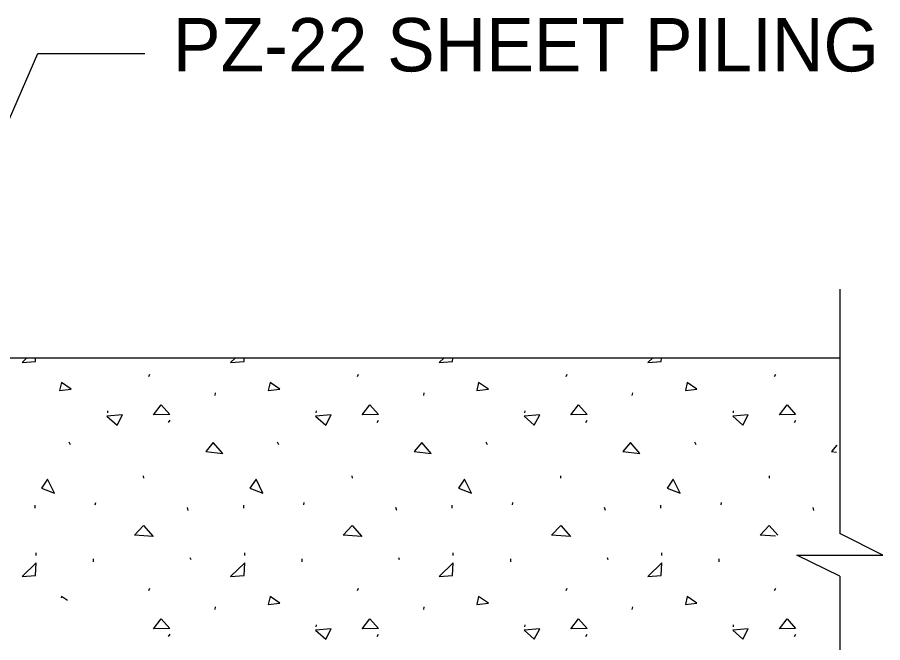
# Model space of a CAD drawing. Extents: x 22369.6 to 22384.3, y 22369.6 to 22381.8.
# Drawn here: x 22375.262 to 22376.018, y 22379.363 to 22379.909 of the extents above; entities that cross this region are included whole.
import ezdxf

# ---------------------------------------------------------------- set-up
doc = ezdxf.new("R2010")
doc.units = 0
for name, color, linetype in [('Level 1', 7, 'Continuous'), ('Level 10', 7, 'Continuous'), ('Level 4', 7, 'Continuous'), ('Level 8', 7, 'Continuous')]:
    doc.layers.add(name, color=color, linetype=linetype)

msp = doc.modelspace()

# ---------------------------------------------------------------- linework, layer by layer
at = {"layer": 'Level 1'}
for p, q in [((22375.05626, 22379.36384), (22375.28013, 22379.87777)), ((22375.28013, 22379.87777), (22375.37359, 22379.87777)), ((22375.98076, 22379.67156), (22375.98076, 22379.45803)), ((22375.98076, 22379.42065), (22375.98076, 22378.74796))]:
    msp.add_line(p, q, dxfattribs=at)
msp.add_lwpolyline([(22375.98076, 22379.42065), (22375.94326, 22379.43928), (22376.01818, 22379.43928), (22375.98076, 22379.45803)], dxfattribs=at)
at = {"layer": 'Level 10'}
msp.add_line((22375.98076, 22379.61141), (22375.02114, 22379.61141), dxfattribs=at)
at = {"layer": 'Level 8'}
for p, q in [((22375.37715, 22379.59544), (22375.37807, 22379.59739)), ((22375.55936, 22379.59544), (22375.56028, 22379.59739)), ((22375.74157, 22379.59544), (22375.74249, 22379.59739)), ((22375.92378, 22379.59544), (22375.9247, 22379.59739)), ((22375.43499, 22379.57864), (22375.43536, 22379.58106)), ((22375.6172, 22379.57864), (22375.61757, 22379.58106)), ((22375.7994, 22379.57864), (22375.79978, 22379.58106)), ((22375.34115, 22379.56344), (22375.34132, 22379.56527)), ((22375.52336, 22379.56344), (22375.52353, 22379.56527)), ((22375.70557, 22379.56344), (22375.70574, 22379.56527)), ((22375.88778, 22379.56344), (22375.88795, 22379.56527)), ((22375.39436, 22379.5551), (22375.39561, 22379.55719)), ((22375.57657, 22379.5551), (22375.57782, 22379.55719)), ((22375.75878, 22379.5551), (22375.76003, 22379.55719)), ((22375.94099, 22379.5551), (22375.94224, 22379.55719)), ((22375.30853, 22379.5356), (22375.3074, 22379.53781)), ((22375.49074, 22379.5356), (22375.48961, 22379.53781)), ((22375.67295, 22379.5356), (22375.67182, 22379.53781)), ((22375.85515, 22379.5356), (22375.85403, 22379.53781)), ((22375.3727, 22379.50656), (22375.37253, 22379.5086)), ((22375.5549, 22379.50656), (22375.55474, 22379.5086)), ((22375.73711, 22379.50656), (22375.73695, 22379.5086)), ((22375.91932, 22379.50656), (22375.91915, 22379.5086)), ((22375.33032, 22379.48319), (22375.33065, 22379.48506)), ((22375.51253, 22379.48319), (22375.51286, 22379.48506)), ((22375.69474, 22379.48319), (22375.69507, 22379.48506)), ((22375.87695, 22379.48319), (22375.87728, 22379.48506)), ((22375.27778, 22379.48023), (22375.27778, 22379.48273)), ((22375.41149, 22379.47823), (22375.41078, 22379.48073)), ((22375.45999, 22379.48023), (22375.45999, 22379.48273)), ((22375.5937, 22379.47823), (22375.59299, 22379.48073)), ((22375.6422, 22379.48023), (22375.6422, 22379.48273)), ((22375.7759, 22379.47823), (22375.7752, 22379.48073)), ((22375.8244, 22379.48023), (22375.8244, 22379.48273)), ((22375.95811, 22379.47823), (22375.9574, 22379.48073)), ((22375.27865, 22379.43877), (22375.27865, 22379.4411)), ((22375.46086, 22379.43877), (22375.46086, 22379.4411)), ((22375.64307, 22379.43877), (22375.64307, 22379.4411)), ((22375.82528, 22379.43877), (22375.82528, 22379.4411)), ((22375.32878, 22379.43339), (22375.32878, 22379.43589)), ((22375.41399, 22379.4351), (22375.41328, 22379.43689)), ((22375.51099, 22379.43339), (22375.51099, 22379.43589)), ((22375.5962, 22379.4351), (22375.59549, 22379.43689)), ((22375.6932, 22379.43339), (22375.6932, 22379.43589)), ((22375.7784, 22379.4351), (22375.7777, 22379.43689)), ((22375.8754, 22379.43339), (22375.8754, 22379.43589)), ((22375.37715, 22379.40839), (22375.37807, 22379.41035)), ((22375.55936, 22379.40839), (22375.56028, 22379.41035)), ((22375.74157, 22379.40839), (22375.74249, 22379.41035)), ((22375.92378, 22379.40839), (22375.9247, 22379.41035)), ((22375.43499, 22379.3916), (22375.43536, 22379.39402)), ((22375.6172, 22379.3916), (22375.61757, 22379.39402)), ((22375.7994, 22379.3916), (22375.79978, 22379.39402)), ((22375.52336, 22379.37639), (22375.52353, 22379.37823)), ((22375.70557, 22379.37639), (22375.70574, 22379.37823)), ((22375.88778, 22379.37639), (22375.88795, 22379.37823)), ((22375.39436, 22379.36806), (22375.39561, 22379.37014)), ((22375.57657, 22379.36806), (22375.57782, 22379.37014)), ((22375.75878, 22379.36806), (22375.76003, 22379.37014)), ((22375.94099, 22379.36806), (22375.94224, 22379.37014))]:
    msp.add_line(p, q, dxfattribs=at)
for points in [[(22375.27032, 22379.61141), (22375.26632, 22379.60752)], [(22375.26632, 22379.60752), (22375.27803, 22379.60844)], [(22375.27803, 22379.60844), (22375.27821, 22379.61141)], [(22375.45253, 22379.61141), (22375.44853, 22379.60752)], [(22375.44853, 22379.60752), (22375.46024, 22379.60844)], [(22375.46024, 22379.60844), (22375.46041, 22379.61141)], [(22375.63473, 22379.61141), (22375.63074, 22379.60752)], [(22375.63074, 22379.60752), (22375.64245, 22379.60844)], [(22375.64245, 22379.60844), (22375.64261, 22379.61141)], [(22375.81694, 22379.61141), (22375.81295, 22379.60752)], [(22375.81295, 22379.60752), (22375.82465, 22379.60844)], [(22375.82465, 22379.60844), (22375.82482, 22379.61141)], [(22375.97813, 22379.53539), (22375.97336, 22379.52973)], [(22375.97336, 22379.52973), (22375.97791, 22379.52923)], [(22375.91115, 22379.45652), (22375.91907, 22379.4651)], [(22375.91907, 22379.4651), (22375.92659, 22379.45669)], [(22375.92461, 22379.45576), (22375.91115, 22379.45652)], [(22375.30078, 22379.40298), (22375.3005, 22379.40174)], [(22375.30611, 22379.39939), (22375.30078, 22379.40298)]]:
    msp.add_lwpolyline(points, dxfattribs=at)
for points in [[(22375.29915, 22379.58302), (22375.30928, 22379.58431), (22375.30078, 22379.59002)], [(22375.48136, 22379.58302), (22375.49149, 22379.58431), (22375.48299, 22379.59002)], [(22375.66357, 22379.58302), (22375.6737, 22379.58431), (22375.6652, 22379.59002)], [(22375.84578, 22379.58302), (22375.8559, 22379.58431), (22375.8474, 22379.59002)], [(22375.38128, 22379.56169), (22375.38799, 22379.57056), (22375.39553, 22379.56202)], [(22375.56349, 22379.56169), (22375.5702, 22379.57056), (22375.57774, 22379.56202)], [(22375.7457, 22379.56169), (22375.7524, 22379.57056), (22375.75995, 22379.56202)], [(22375.9279, 22379.56169), (22375.93461, 22379.57056), (22375.94215, 22379.56202)], [(22375.34053, 22379.56073), (22375.3494, 22379.55281), (22375.35415, 22379.56169)], [(22375.52274, 22379.56073), (22375.53161, 22379.55281), (22375.53636, 22379.56169)], [(22375.70495, 22379.56073), (22375.71382, 22379.55281), (22375.71857, 22379.56169)], [(22375.88715, 22379.56073), (22375.89603, 22379.55281), (22375.90078, 22379.56169)], [(22375.44161, 22379.5281), (22375.43336, 22379.5376), (22375.42674, 22379.52973)], [(22375.62382, 22379.5281), (22375.61557, 22379.5376), (22375.60895, 22379.52973)], [(22375.80603, 22379.5281), (22375.79778, 22379.5376), (22375.79115, 22379.52973)], [(22375.2832, 22379.49773), (22375.29457, 22379.49331), (22375.28857, 22379.5056)], [(22375.4654, 22379.49773), (22375.47678, 22379.49331), (22375.47078, 22379.5056)], [(22375.64761, 22379.49773), (22375.65899, 22379.49331), (22375.65299, 22379.5056)], [(22375.82982, 22379.49773), (22375.8412, 22379.49331), (22375.8352, 22379.5056)], [(22375.36453, 22379.45652), (22375.37245, 22379.4651), (22375.38095, 22379.4556)], [(22375.54674, 22379.45652), (22375.55465, 22379.4651), (22375.56315, 22379.4556)], [(22375.72895, 22379.45652), (22375.73686, 22379.4651), (22375.74536, 22379.4556)], [(22375.27803, 22379.42139), (22375.27865, 22379.43252), (22375.26632, 22379.42048)], [(22375.46024, 22379.42139), (22375.46086, 22379.43252), (22375.44853, 22379.42048)], [(22375.64245, 22379.42139), (22375.64307, 22379.43252), (22375.63074, 22379.42048)], [(22375.82465, 22379.42139), (22375.82528, 22379.43252), (22375.81295, 22379.42048)], [(22375.48136, 22379.39598), (22375.49149, 22379.39727), (22375.48299, 22379.40298)], [(22375.66357, 22379.39598), (22375.6737, 22379.39727), (22375.6652, 22379.40298)], [(22375.84578, 22379.39598), (22375.8559, 22379.39727), (22375.8474, 22379.40298)], [(22375.38128, 22379.37464), (22375.38799, 22379.38352), (22375.39553, 22379.37498)], [(22375.56349, 22379.37464), (22375.5702, 22379.38352), (22375.57774, 22379.37498)], [(22375.7457, 22379.37464), (22375.7524, 22379.38352), (22375.75995, 22379.37498)], [(22375.9279, 22379.37464), (22375.93461, 22379.38352), (22375.94215, 22379.37498)], [(22375.52274, 22379.37369), (22375.53161, 22379.36577), (22375.53636, 22379.37464)], [(22375.70495, 22379.37369), (22375.71382, 22379.36577), (22375.71857, 22379.37464)], [(22375.88715, 22379.37369), (22375.89603, 22379.36577), (22375.90078, 22379.37464)]]:
    msp.add_lwpolyline(points, close=True, dxfattribs=at)

# ---------------------------------------------------------------- texts
at = {"layer": 'Level 4'}
msp.add_text('PZ-22 SHEET PILING', height=0.046625, dxfattribs=at).set_placement((22375.39818, 22379.86201))

doc.saveas('drawing.dxf')
